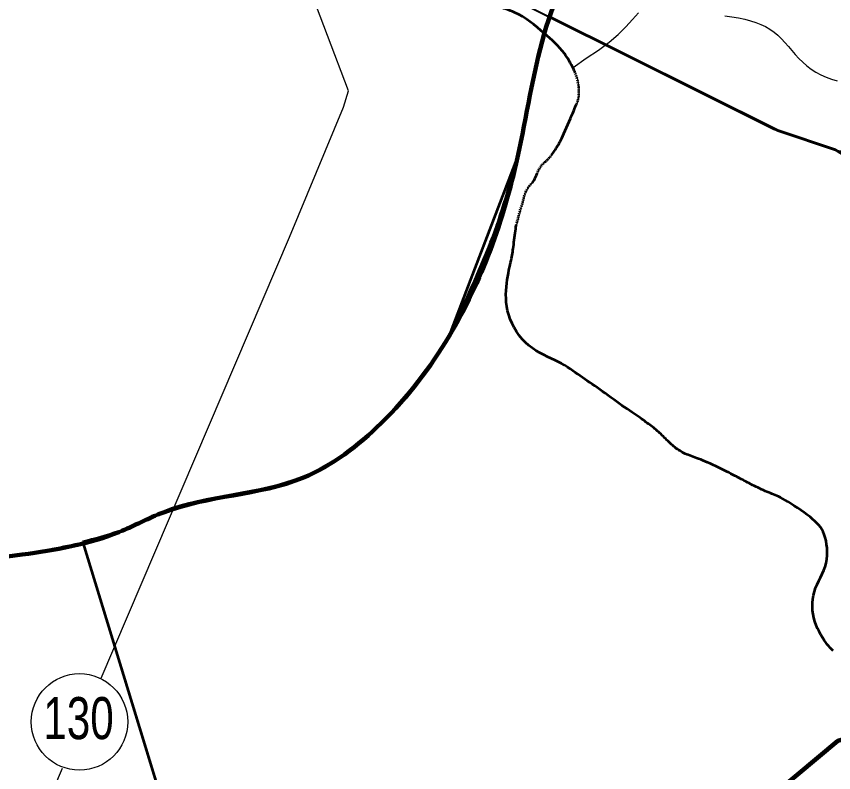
# Model space of a CAD drawing. Extents: x -1643653 to 4543381, y 1624270 to 13878484.
# Drawn here: x 690536 to 697335, y 8955793 to 8962082 of the extents above; entities that cross this region are included whole.
import ezdxf
from ezdxf.enums import TextEntityAlignment as Align

# ---------------------------------------------------------------- set-up
doc = ezdxf.new("R2010")
doc.units = 0
doc.header["$LTSCALE"] = 200
for name, color, linetype, lineweight in [('12', 7, 'Continuous', 25), ('24', 7, 'Continuous', 25), ('26', 7, 'Continuous', 106), ('28', 7, 'Continuous', 53), ('48', 7, 'Continuous', 25), ('60', 7, 'Continuous', 13), ('9', 7, 'Continuous', 90)]:
    doc.layers.add(name, color=color, linetype=linetype, lineweight=lineweight)

msp = doc.modelspace()

# ---------------------------------------------------------------- linework, layer by layer
at = {"layer": '12'}
for points in [[(691240.8, 8956578.2), (692809.2, 8960246.9), (693257.6, 8961326.5), (693299.9, 8961463.3), (692951.1, 8962385.1), (692776, 8962756.9), (692786.9, 8963010.2)], [(686961.1, 8947176.1), (688051.1, 8949196.4), (690022.8, 8953729), (690920.6, 8955829.2)]]:
    msp.add_lwpolyline(points, dxfattribs=at)
at = {"layer": '12', "lineweight": 40}
msp.add_lwpolyline([(693487.4, 8962819.8), (696836.9, 8961144.8), (697384.1, 8960961.8), (697603.7, 8960973.6), (697714.4, 8961082.3), (698321.2, 8961447.4), (698679, 8961567.8), (700187.3, 8961472.5), (701093.5, 8961547), (704410.2, 8961560.7)], dxfattribs=at)
at = {"layer": '24'}
for p, q in [((695185.1, 8961613.6), (695188.4, 8961605.4)), ((695191.4, 8961597.4), (695194.2, 8961589.4)), ((695196.8, 8961581.3), (695199.3, 8961572.8)), ((695201.7, 8961563.9), (695204, 8961554.7)), ((695206.1, 8961545.2), (695208.1, 8961535.5)), ((695210, 8961525.8), (695211.6, 8961516.2)), ((695213.1, 8961506.8), (695214.2, 8961497.7)), ((695215.1, 8961489), (695215.8, 8961480.6)), ((695216.2, 8961443), (695215.9, 8961436)), ((695216.2, 8961472.6), (695216.5, 8961464.9)), ((695216.5, 8961457.4), (695216.4, 8961450.1)), ((695208.8, 8961386.1), (695206.5, 8961378.2)), ((695212.3, 8961401), (695210.8, 8961393.7)), ((695214.3, 8961415.2), (695213.5, 8961408.2)), ((695215.5, 8961429.1), (695215, 8961422.2)), ((695203.7, 8961369.9), (695200.3, 8961361)), ((694966.8, 8960901.5), (694962.4, 8960896.8)), ((694976.7, 8960913), (694971.5, 8960906.9)), ((694988.2, 8960928.1), (694982.2, 8960920.1)), ((694895.4, 8960829.4), (694891.8, 8960823.7)), ((694903.2, 8960840.2), (694899.2, 8960834.8)), ((694912.2, 8960850.5), (694907.6, 8960845.4)), ((694922.1, 8960860.3), (694917.1, 8960855.5)), ((694932, 8960869.5), (694927, 8960865)), ((694941.4, 8960877.7), (694936.8, 8960873.7)), ((694950, 8960885.1), (694945.8, 8960881.5)), ((694958.2, 8960892.6), (694954.1, 8960888.7)), ((694874.5, 8960788.4), (694870.7, 8960779.5)), ((694881.6, 8960804.2), (694878.1, 8960796.7)), ((694888.3, 8960817.6), (694885, 8960811.2)), ((694825.8, 8960695.7), (694819.7, 8960688.5)), ((694781.6, 8960638.2), (694777.4, 8960629.7)), ((694790.9, 8960654), (694786, 8960646.3)), ((694801.8, 8960668.2), (694796.2, 8960661.2)), ((694813.6, 8960681.6), (694807.6, 8960674.9)), ((694756.5, 8960567.7), (694754.3, 8960559.1)), ((694761.3, 8960585.2), (694758.9, 8960576.3)), ((694767, 8960603.1), (694764, 8960594.1)), ((694773.6, 8960621), (694770.2, 8960612.1)), ((694738.8, 8960501.8), (694736.3, 8960493.8)), ((694743.7, 8960517.7), (694741.3, 8960509.7)), ((694748.1, 8960534), (694745.9, 8960525.8)), ((694752.2, 8960550.6), (694750.2, 8960542.3)), ((694715.5, 8960421.7), (694713.5, 8960413.8)), ((694719.5, 8960437.8), (694717.4, 8960429.8)), ((694723.8, 8960454.1), (694721.6, 8960446)), ((694728.6, 8960470), (694726.2, 8960462.1)), ((694733.8, 8960485.9), (694731.2, 8960478)), ((694699.2, 8960361.1), (694696.9, 8960351.9)), ((694703.5, 8960376.8), (694701.4, 8960369.2)), ((694707.7, 8960391.1), (694705.6, 8960383.9)), ((694711.6, 8960406), (694709.7, 8960398.4))]:
    msp.add_line(p, q, dxfattribs=at)
at = {"layer": '24', "lineweight": 53}
for p, q in [((695191.4, 8961597.4), (695188.4, 8961605.4)), ((695196.8, 8961581.3), (695194.2, 8961589.4)), ((695201.7, 8961563.9), (695199.3, 8961572.8)), ((695206.1, 8961545.2), (695204, 8961554.7)), ((695210, 8961525.8), (695208.1, 8961535.5)), ((695213.1, 8961506.8), (695211.6, 8961516.2)), ((695215.1, 8961489), (695214.2, 8961497.7)), ((695216.2, 8961472.6), (695215.8, 8961480.6)), ((695216.2, 8961443), (695216.4, 8961450.1)), ((695216.5, 8961457.4), (695216.5, 8961464.9)), ((695203.7, 8961369.9), (695206.5, 8961378.2)), ((695208.8, 8961386.1), (695210.8, 8961393.7)), ((695212.3, 8961401), (695213.5, 8961408.2)), ((695214.3, 8961415.2), (695215, 8961422.2)), ((695215.5, 8961429.1), (695215.9, 8961436)), ((694958.2, 8960892.6), (694962.4, 8960896.8)), ((694966.8, 8960901.5), (694971.5, 8960906.9)), ((694976.7, 8960913), (694982.2, 8960920.1)), ((694895.4, 8960829.4), (694899.2, 8960834.8)), ((694903.2, 8960840.2), (694907.6, 8960845.4)), ((694912.2, 8960850.5), (694917.1, 8960855.5)), ((694922.1, 8960860.3), (694927, 8960865)), ((694932, 8960869.5), (694936.8, 8960873.7)), ((694941.4, 8960877.7), (694945.8, 8960881.5)), ((694950, 8960885.1), (694954.1, 8960888.7)), ((694874.5, 8960788.4), (694878.1, 8960796.7)), ((694881.6, 8960804.2), (694885, 8960811.2)), ((694888.3, 8960817.6), (694891.8, 8960823.7)), ((694773.6, 8960621), (694777.4, 8960629.7)), ((694781.6, 8960638.2), (694786, 8960646.3)), ((694790.9, 8960654), (694796.2, 8960661.2)), ((694801.8, 8960668.2), (694807.6, 8960674.9)), ((694813.6, 8960681.6), (694819.7, 8960688.5)), ((694752.2, 8960550.6), (694754.3, 8960559.1)), ((694756.5, 8960567.7), (694758.9, 8960576.3)), ((694761.3, 8960585.2), (694764, 8960594.1)), ((694767, 8960603.1), (694770.2, 8960612.1)), ((694733.8, 8960485.9), (694736.3, 8960493.8)), ((694738.8, 8960501.8), (694741.3, 8960509.7)), ((694743.7, 8960517.7), (694745.9, 8960525.8)), ((694748.1, 8960534), (694750.2, 8960542.3)), ((694715.5, 8960421.7), (694717.4, 8960429.8)), ((694719.5, 8960437.8), (694721.6, 8960446)), ((694723.8, 8960454.1), (694726.2, 8960462.1)), ((694728.6, 8960470), (694731.2, 8960478)), ((694699.2, 8960361.1), (694701.4, 8960369.2)), ((694703.5, 8960376.8), (694705.6, 8960383.9)), ((694707.7, 8960391.1), (694709.7, 8960398.4)), ((694711.6, 8960406), (694713.5, 8960413.8))]:
    msp.add_line(p, q, dxfattribs=at)
at = {"layer": '24'}
for points in [[(695169, 8961656.4), (695276, 8961734.9), (695379, 8961800.8), (695467.1, 8961866.7), (695542.4, 8961931.7), (695606.8, 8961994.7), (695662.7, 8962054.9), (695711.8, 8962111.2)], [(696430.6, 8962086.5), (696489, 8962078.1), (696543.7, 8962068.8), (696595, 8962058.2), (696643, 8962046), (696688, 8962031.9), (696729.9, 8962015.6), (696769, 8961997.1), (696805.5, 8961975.9), (696839.5, 8961951.8), (696871.2, 8961924.8), (696901.1, 8961895.4), (696929.9, 8961864), (696958.1, 8961831.5), (696986.4, 8961798.2), (697015.3, 8961765), (697045.4, 8961732.3), (697077.4, 8961700.9), (697111.7, 8961671.2), (697148.3, 8961643.6), (697187.3, 8961618.4), (697228.5, 8961595.8)], [(695116.9, 8961748), (695124.2, 8961736.8), (695131.2, 8961725.1), (695138.1, 8961712.9), (695144.8, 8961700.5), (695151.1, 8961688), (695157.2, 8961675.6), (695162.9, 8961663.6), (695168.2, 8961652.1)], [(697228.5, 8961595.8), (697272, 8961576.2), (697317.5, 8961559.7), (697365.1, 8961546.7)]]:
    msp.add_lwpolyline(points, dxfattribs=at)
at = {"layer": '24', "lineweight": 53}
for points in [[(695185.1, 8961613.6), (695181.5, 8961622.3), (695177.5, 8961631.4), (695173.1, 8961641.4), (695168.2, 8961652.1)], [(694988.2, 8960928.1), (694994.5, 8960936.7), (695001, 8960945.8), (695007.6, 8960955.3), (695014.2, 8960965), (695020.7, 8960974.9), (695027, 8960984.7), (695033.1, 8960994.3), (695039.1, 8961004.1), (695045.1, 8961014.5), (695051.4, 8961025.8), (695057.9, 8961038.3), (695065, 8961052.5), (695072.8, 8961068.8), (695081.4, 8961087.4), (695091, 8961108.7), (695101.2, 8961132), (695112, 8961156.7), (695123, 8961182.2), (695134, 8961207.7), (695144.6, 8961232.5), (695154.7, 8961256.1), (695164, 8961277.6), (695172.3, 8961296.5), (695179.6, 8961313), (695186, 8961327.5), (695191.5, 8961340.1), (695196.2, 8961351.1), (695200.3, 8961361)], [(694825.8, 8960695.7), (694831.7, 8960703.3), (694837.5, 8960711.5), (694843, 8960720.4), (694848.2, 8960730), (694853.2, 8960739.8), (694858, 8960749.9), (694862.5, 8960760), (694866.7, 8960769.9), (694870.7, 8960779.5)], [(694610.5, 8959801.8), (694612.9, 8959833), (694616.2, 8959863.1), (694620.1, 8959891.9), (694624.3, 8959919.5), (694628.9, 8959945.6), (694633.6, 8959970.2), (694638.3, 8959993.2), (694642.9, 8960014.6), (694647.3, 8960034.3), (694651.3, 8960052.2), (694654.8, 8960068.3), (694657.9, 8960082.9), (694660.6, 8960096.7), (694663.1, 8960109.9), (694665.3, 8960123.1), (694667.5, 8960136.7), (694669.5, 8960151.2), (694671.6, 8960167.1), (694673.7, 8960184.6), (694675.9, 8960203.4), (694678.2, 8960223), (694680.5, 8960243), (694682.8, 8960262.7), (694685.2, 8960281.7), (694687.6, 8960299.4), (694689.9, 8960315.5), (694692.3, 8960329.4), (694694.6, 8960341.5), (694696.9, 8960351.9)], [(695412.6, 8958963.5), (695390.1, 8958979.4), (695368.3, 8958994.5), (695347.1, 8959009), (695326.3, 8959023.1), (695305.9, 8959036.8), (695285.8, 8959050.4), (695265.9, 8959063.9), (695246.1, 8959077.5), (695226.2, 8959091.4), (695206.1, 8959105.7), (695185.8, 8959120.3), (695164.8, 8959135.2), (695143.1, 8959150.1), (695120.4, 8959165), (695096.6, 8959179.9), (695071.3, 8959194.5), (695044.4, 8959208.8), (695015.8, 8959222.9), (694985.9, 8959236.9), (694954.9, 8959251.4), (694923.4, 8959266.7), (694891.7, 8959283.3), (694860.2, 8959301.5), (694829.4, 8959321.8), (694799.7, 8959344.6), (694771.4, 8959370.2), (694744.8, 8959398.3), (694720.1, 8959428.6), (694697.5, 8959460.6), (694677.2, 8959494), (694659.3, 8959528.4), (694644.1, 8959563.4), (694631.8, 8959598.6), (694622.4, 8959633.7), (694615.8, 8959668.4), (694611.6, 8959702.8), (694609.5, 8959736.5), (694609.3, 8959769.6), (694610.5, 8959801.8)], [(695976.9, 8958531), (695967.2, 8958540.1), (695957.7, 8958549.4), (695948.1, 8958558.9), (695938.5, 8958568.5), (695928.9, 8958578.1), (695919.2, 8958587.8), (695909.4, 8958597.3), (695899.5, 8958606.6), (695889.5, 8958615.8), (695879.4, 8958624.8), (695869.1, 8958633.6), (695858.8, 8958642.3), (695848.4, 8958650.8), (695837.9, 8958659.2), (695827.4, 8958667.5), (695816.9, 8958675.7), (695806.4, 8958683.8), (695795.7, 8958692), (695784.8, 8958700.2), (695773.5, 8958708.6), (695761.6, 8958717.3), (695749.1, 8958726.3), (695735.9, 8958735.7), (695721.7, 8958745.6), (695706.5, 8958756), (695690.3, 8958767), (695673.1, 8958778.7), (695655, 8958791), (695636, 8958803.9), (695616.2, 8958817.6), (695595.5, 8958832), (695574, 8958847.1), (695551.8, 8958862.9), (695529, 8958879.4), (695505.8, 8958896.2), (695482.3, 8958913.2), (695458.9, 8958930.2), (695435.6, 8958947.1), (695412.6, 8958963.5)], [(696565.6, 8958234), (696553, 8958240.7), (696540.1, 8958247.5), (696526.7, 8958254.6), (696512.5, 8958262), (696497.3, 8958269.9), (696480.9, 8958278.4), (696462.9, 8958287.6), (696443.2, 8958297.7), (696422.1, 8958308.3), (696399.9, 8958319.3), (696377.1, 8958330.5), (696354, 8958341.7), (696331, 8958352.5), (696308.5, 8958362.8), (696286.8, 8958372.3), (696266.3, 8958381), (696247, 8958388.7), (696228.8, 8958395.7), (696211.6, 8958402.1), (696195.3, 8958408), (696179.9, 8958413.6), (696165.2, 8958418.8), (696151.3, 8958424), (696138, 8958429.1), (696125.3, 8958434.3), (696113, 8958439.6), (696101.2, 8958445), (696089.8, 8958450.5), (696078.8, 8958456.3), (696067.9, 8958462.3), (696057.3, 8958468.6), (696046.9, 8958475.3), (696036.5, 8958482.3), (696026.3, 8958489.6), (696016.2, 8958497.3), (696006.3, 8958505.3), (695996.4, 8958513.5), (695986.6, 8958522.1), (695976.9, 8958531)], [(697236.7, 8957815.1), (697224.9, 8957833.8), (697211.5, 8957851.4), (697196.4, 8957868.2), (697179.4, 8957884.7), (697160.2, 8957901.4), (697138.7, 8957918.7), (697114.9, 8957936.9), (697089.2, 8957955.7), (697062.3, 8957974.8), (697034.9, 8957993.6), (697007.6, 8958011.9), (696981, 8958029.1), (696955.8, 8958044.8), (696932.7, 8958058.6), (696912.1, 8958070.2), (696893.7, 8958079.8), (696877.2, 8958087.9), (696862.2, 8958094.6), (696848.2, 8958100.5), (696834.9, 8958105.8), (696821.7, 8958110.9), (696808.4, 8958116.1), (696794.5, 8958121.7), (696780.1, 8958127.8), (696765.2, 8958134.2), (696750.2, 8958141), (696734.9, 8958148), (696719.6, 8958155.2), (696704.3, 8958162.5), (696689.2, 8958169.8), (696674.4, 8958177.2), (696659.8, 8958184.6), (696645.5, 8958191.9), (696631.5, 8958199.1), (696617.8, 8958206.3), (696604.3, 8958213.4), (696591.2, 8958220.4), (696578.3, 8958227.2), (696565.6, 8958234)], [(697331.3, 8956805.9), (697323.2, 8956813.3), (697314.3, 8956822.1), (697304.5, 8956832.4), (697293.7, 8956844.7), (697281.9, 8956859.2), (697269, 8956876.1), (697255.3, 8956895.4), (697241.2, 8956916.7), (697227.2, 8956940), (697213.5, 8956965.1), (697200.6, 8956991.7), (697188.9, 8957019.6), (697178.8, 8957048.7), (697170.6, 8957078.7), (697164.4, 8957109.5), (697160.3, 8957140.9), (697158.5, 8957172.5), (697159, 8957204.3), (697161.8, 8957236), (697167.1, 8957267.4), (697175, 8957298.3), (697185.4, 8957328.5), (697197.7, 8957358.2), (697211.2, 8957387.5), (697225.2, 8957416.7), (697239.1, 8957446), (697252, 8957475.4), (697263.2, 8957505.3), (697272.1, 8957535.8), (697278.2, 8957567), (697281.4, 8957598.5), (697282.1, 8957630), (697280.5, 8957661.1), (697276.8, 8957691.2), (697271.4, 8957720), (697264.5, 8957747.1), (697256.3, 8957772.1), (697247.1, 8957794.6), (697236.7, 8957815.1)]]:
    msp.add_lwpolyline(points, dxfattribs=at)
msp.add_spline([(695170.7, 8961646.8), (695094.7, 8961773.3), (694929.1, 8961938.8), (694680.8, 8962114.8), (694540.3, 8962171.7), (694427.3, 8962232.6), (694366.5, 8962247.8), (694270.9, 8962269.5), (694127.6, 8962297.8), (693938.6, 8962389.1), (693764.8, 8962478.2), (693575.8, 8962545.5), (693330.4, 8962615.1), (693210.9, 8962636.8), (692989.3, 8962745.5), (692906.8, 8962786.8), (692817.7, 8962838.9), (692765.6, 8962886.7), (692691.7, 8962969.3), (692639.6, 8963030.2), (692544, 8963141), (692498.4, 8963178), (692402.8, 8963258.4), (692300.7, 8963319.2), (692140, 8963421.4), (691977.1, 8963493.1), (691866.3, 8963514.8), (691638.2, 8963532.2), (691462.3, 8963549.6), (691336.3, 8963562.6), (691273.3, 8963588.7), (691203.8, 8963640.9), (691103.8, 8963762.6), (691048.1, 8963842.5), (691024.9, 8963935.4), (691027.8, 8964068.8), (691022, 8964216.8), (690966.8, 8964338.7), (690920.4, 8964422.8), (690914.6, 8964530.2), (690952.3, 8964623), (691022, 8964721.7), (691088.7, 8964808.7), (691297.6, 8965101.8), (691483.3, 8965383.2), (691582, 8965539.9), (691761.8, 8965929.2), (692017.2, 8966518.5), (692139.1, 8966942.3), (692231.9, 8967543.3), (692246.4, 8967740.7), (692124.5, 8967943.9), (691973.7, 8968039.7), (691700.9, 8968077.4), (691448.5, 8968103.5)], degree=3, dxfattribs=at)
at = {"layer": '26'}
for points in [[(676174.9, 8960921), (676589.7, 8959851), (677298.5, 8959085), (677905.7, 8958370.4), (678108.1, 8958127.9), (678628.8, 8957871.5), (679175.3, 8957678.5), (679634.1, 8957740.2), (680271.7, 8957890.1), (680680.6, 8958130.1), (682556.7, 8958821.8), (683435.7, 8958881.7), (684580.7, 8958673.6), (685598.3, 8958453.2), (686374.5, 8958348.3), (687212.1, 8957836.1), (687682.2, 8957630.7), (688306.1, 8957615.5), (689591.9, 8957533.9), (690585.7, 8957606.1), (691389.1, 8957793.5), (691759.3, 8957957.3), (692919.9, 8958245), (693572, 8958700.2), (694136.4, 8959422.7), (694705.3, 8960908.2), (694927.7, 8961937.4), (695327.4, 8962800.5), (695494.2, 8963028.7), (696954.2, 8966672.4), (698159, 8968028.2), (699003.1, 8968647.8), (699373.7, 8968875.2), (699705.8, 8969051.9), (700930.8, 8969479.2), (701631.8, 8969565.3), (702395, 8969409.6), (703157, 8969037.7), (703804.2, 8968640.8), (704732, 8968306.3), (704974.2, 8968343.5), (705432.6, 8968328.9), (706400.3, 8968312.2), (707482.9, 8968320.5), (708005.4, 8968381.9), (708718.3, 8968340.8), (709660.3, 8968260.6), (710627.7, 8968180.3), (711187.5, 8968089), (711873, 8967704.7), (712851.5, 8967319.2), (713361.3, 8967393.4), (714238.5, 8967122.7), (715674, 8966506.4), (716373.4, 8966312.8), (717313.4, 8965902), (718673.1, 8965375), (719658.3, 8965140.1)], [(691088.7, 8957705.7), (691389.1, 8957793.5), (691759.3, 8957957.3), (692919.9, 8958245), (693572, 8958700.2), (694136.4, 8959422.7), (694705.3, 8960908.2), (694927.7, 8961937.4), (695327.4, 8962800.5), (695494.2, 8963028.7), (696954.2, 8966672.4), (698159, 8968028.2), (699003.1, 8968647.8), (699373.7, 8968875.2), (699705.8, 8969051.9), (700930.8, 8969479.2), (701631.8, 8969565.3), (702395, 8969409.6), (703157, 8969037.7), (703804.2, 8968640.8), (704732, 8968306.3), (704974.2, 8968343.5), (705432.6, 8968328.9), (706400.3, 8968312.2), (707482.9, 8968320.5), (708005.4, 8968381.9), (708718.3, 8968340.8), (709660.3, 8968260.6), (710627.7, 8968180.3), (711187.5, 8968089), (711873, 8967704.7), (712851.5, 8967319.2), (713361.3, 8967393.4), (714238.5, 8967122.7), (715674, 8966506.4), (716373.4, 8966312.8), (717313.4, 8965902), (718673.1, 8965375), (719658.3, 8965140.1)]]:
    msp.add_spline(points, degree=3, dxfattribs=at)
at = {"layer": '28'}
for p, q in [((694975.6, 8962075.5), (694975.7, 8962075.5)), ((694136.4, 8959422.7), (694705.3, 8960908.2)), ((691088.7, 8957705.7), (693972.6, 8948277.3))]:
    msp.add_line(p, q, dxfattribs=at)
for points in [[(703803.2, 8956817.2), (697349.9, 8960973.2), (696869.5, 8961133.9), (694975.7, 8962075.5), (694975.6, 8962075.5)], [(694975.7, 8962075.5), (696869.5, 8961133.9), (697349.9, 8960973.2), (703803.2, 8956817.2), (704507.1, 8956833.9), (704545.8, 8956841.3), (705332.5, 8957133.3), (705449.4, 8957176.7), (705509.2, 8957238.1), (705586.2, 8957463.2)], [(691088.7, 8957705.7), (691088.7, 8957705.7), (693972.6, 8948277.3)]]:
    msp.add_lwpolyline(points, dxfattribs=at)
for points in [[(707482.9, 8968320.5), (706400.3, 8968312.2), (705432.6, 8968328.9), (704974.2, 8968343.5), (704732, 8968306.3), (703804.2, 8968640.8), (703157, 8969037.7), (702395, 8969409.6), (701631.8, 8969565.3), (700930.8, 8969479.2), (699705.8, 8969051.9), (699373.7, 8968875.2), (699003.1, 8968647.8), (698159, 8968028.2), (696954.2, 8966672.4), (695494.2, 8963028.7), (695327.4, 8962800.5), (694975.6, 8962075.5)], [(694975.6, 8962075.5), (694927.7, 8961937.4), (694705.3, 8960908.2), (694136.4, 8959422.7)], [(694705.3, 8960908.2), (694136.4, 8959422.7), (693572, 8958700.2), (692919.9, 8958245), (691759.3, 8957957.3), (691389.1, 8957793.5), (691088.7, 8957705.7)], [(688743.6, 8957587), (689591.9, 8957533.9), (690585.7, 8957606.1), (691088.7, 8957705.7)]]:
    msp.add_spline(points, degree=3, dxfattribs=at)
at = {"layer": '48'}
msp.add_circle((691061.1, 8956214.5), 401.3, dxfattribs=at)
at = {"layer": '60', "lineweight": 25}
msp.add_spline([(814781, 9009175.5), (814787.2, 9009173.4), (814796.9, 9009173.4), (814799.4, 9009172.4), (814805.1, 9009174.5), (814805.6, 9009176.5), (814811.7, 9009179.5), (814811.7, 9009179.5), (814801.5, 9009181), (814790.7, 9009181.5), (814784.1, 9009183.1), (814777.4, 9009185.1), (814778.4, 9009175.5)], degree=3, dxfattribs=at)
at = {"layer": '9'}
msp.add_lwpolyline([(691582, 8951218.7), (697371.2, 8956056), (705081.2, 8958366.8), (713138.6, 8969695)], dxfattribs=at)
for points in [[(637260.6, 8972975.8), (641524.5, 8971056.2), (652526.1, 8965412.7), (653164.3, 8965062.8), (670790.5, 8953770.1), (686194, 8943929.9), (696283.3, 8937647.1)], [(694874, 8947402.7), (694491.4, 8947729), (693981.6, 8948105.1), (692654.2, 8949437.3), (691811.8, 8950292), (691552.9, 8951277.6), (691093.4, 8951755.3), (689976, 8951721.8), (689441.2, 8951996.3), (689158.9, 8952576.6), (688699.5, 8953029), (687605.5, 8953400.8), (685873.4, 8954400.8), (684752.3, 8955101.5), (681638, 8958243.7), (680641.1, 8959527.7), (679425.4, 8960995.9)]]:
    msp.add_spline(points, degree=3, dxfattribs=at)

# ---------------------------------------------------------------- texts
at = {"layer": '48', "width": 0.75}
msp.add_text('130', height=350, dxfattribs=at).set_placement((691053.4, 8956071), align=Align.CENTER)

doc.saveas('drawing.dxf')
